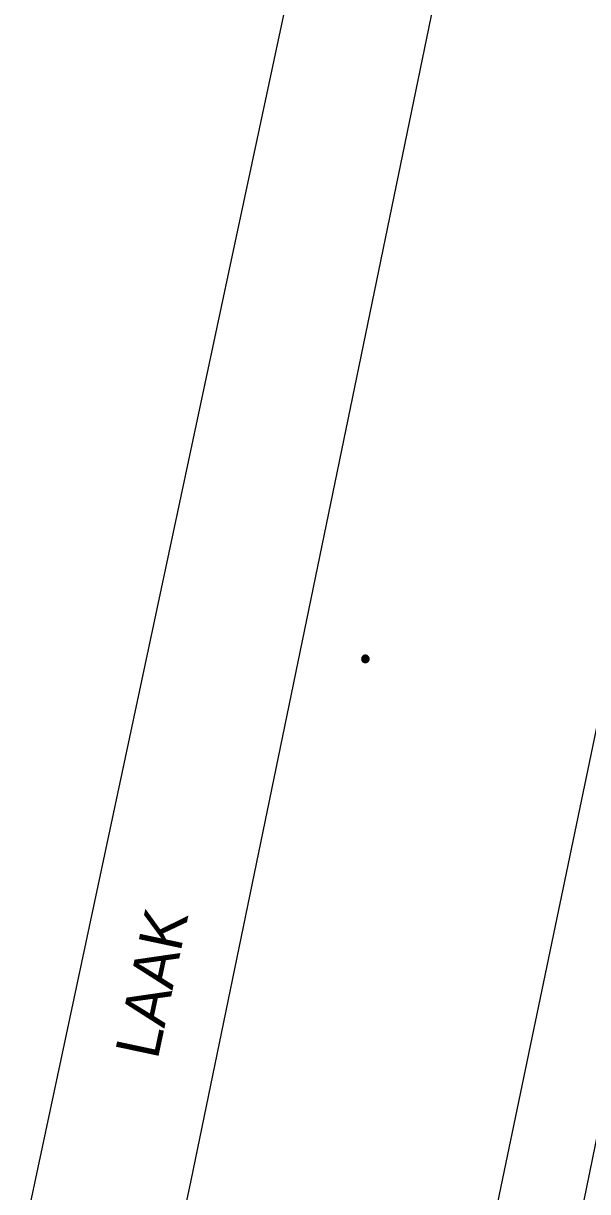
# Model space of a CAD drawing. Extents: x 81065 to 81486, y 452384 to 452681.
# Drawn here: x 81256.82 to 81276.27, y 452560.19 to 452600.46 of the extents above; entities that cross this region are included whole.
import ezdxf

# ---------------------------------------------------------------- set-up
doc = ezdxf.new("R2010")
doc.units = 0
for name, color, linetype in [('B-BH-AL-TOPOGRAFIE_STRAATNAAM-S', 7, 'Continuous'), ('B-BH-GR-BOOM-S', 7, 'Continuous'), ('B-BH-GR-GROENVOORZIENING-GV', 7, 'Continuous'), ('B-BH-VH-KANTOPSLUITING-GV', 7, 'Continuous')]:
    doc.layers.add(name, color=color, linetype=linetype)

msp = doc.modelspace()

# ---------------------------------------------------------------- linework, layer by layer
at = {"layer": 'B-BH-GR-BOOM-S'}
for points in [[(81268.479, 452578.55), (81268.48, 452578.536), (81268.482, 452578.523), (81268.485, 452578.51), (81268.49, 452578.498), (81268.496, 452578.486), (81268.504, 452578.474), (81268.512, 452578.464), (81268.522, 452578.454), (81268.532, 452578.446), (81268.544, 452578.438), (81268.556, 452578.432), (81268.568, 452578.427), (81268.581, 452578.424), (81268.594, 452578.422), (81268.608, 452578.421), (81268.621, 452578.422), (81268.635, 452578.424), (81268.648, 452578.427), (81268.66, 452578.432), (81268.672, 452578.438), (81268.684, 452578.446), (81268.694, 452578.454), (81268.704, 452578.464), (81268.712, 452578.474), (81268.72, 452578.486), (81268.726, 452578.498), (81268.73, 452578.51), (81268.734, 452578.523), (81268.736, 452578.536), (81268.737, 452578.55), (81268.736, 452578.563), (81268.734, 452578.577), (81268.73, 452578.59), (81268.726, 452578.602), (81268.72, 452578.614), (81268.712, 452578.626), (81268.704, 452578.636), (81268.694, 452578.646), (81268.684, 452578.654), (81268.672, 452578.662), (81268.66, 452578.668), (81268.648, 452578.672), (81268.635, 452578.676), (81268.621, 452578.678), (81268.608, 452578.679), (81268.594, 452578.678), (81268.581, 452578.676), (81268.568, 452578.672), (81268.556, 452578.668), (81268.544, 452578.662), (81268.532, 452578.654), (81268.522, 452578.646), (81268.512, 452578.636), (81268.504, 452578.626), (81268.496, 452578.614), (81268.49, 452578.602), (81268.485, 452578.59), (81268.482, 452578.577), (81268.48, 452578.563), (81268.479, 452578.55)], [(81268.504, 452578.55), (81268.504, 452578.539), (81268.506, 452578.528), (81268.509, 452578.518), (81268.513, 452578.507), (81268.517, 452578.498), (81268.523, 452578.489), (81268.53, 452578.48), (81268.538, 452578.472), (81268.547, 452578.465), (81268.556, 452578.459), (81268.565, 452578.455), (81268.576, 452578.451), (81268.586, 452578.448), (81268.597, 452578.446), (81268.608, 452578.446), (81268.619, 452578.446), (81268.63, 452578.448), (81268.64, 452578.451), (81268.65, 452578.455), (81268.66, 452578.459), (81268.669, 452578.465), (81268.678, 452578.472), (81268.686, 452578.48), (81268.692, 452578.489), (81268.698, 452578.498), (81268.703, 452578.507), (81268.707, 452578.518), (81268.71, 452578.528), (81268.712, 452578.539), (81268.712, 452578.55), (81268.712, 452578.561), (81268.71, 452578.572), (81268.707, 452578.582), (81268.703, 452578.592), (81268.698, 452578.602), (81268.692, 452578.611), (81268.686, 452578.62), (81268.678, 452578.628), (81268.669, 452578.634), (81268.66, 452578.64), (81268.65, 452578.645), (81268.64, 452578.649), (81268.63, 452578.652), (81268.619, 452578.654), (81268.608, 452578.654), (81268.597, 452578.654), (81268.586, 452578.652), (81268.576, 452578.649), (81268.565, 452578.645), (81268.556, 452578.64), (81268.547, 452578.634), (81268.538, 452578.628), (81268.53, 452578.62), (81268.523, 452578.611), (81268.517, 452578.602), (81268.513, 452578.592), (81268.509, 452578.582), (81268.506, 452578.572), (81268.504, 452578.561), (81268.504, 452578.55)], [(81268.526, 452578.55), (81268.527, 452578.541), (81268.528, 452578.533), (81268.53, 452578.525), (81268.533, 452578.517), (81268.537, 452578.509), (81268.542, 452578.502), (81268.547, 452578.495), (81268.553, 452578.489), (81268.56, 452578.484), (81268.567, 452578.479), (81268.575, 452578.475), (81268.583, 452578.472), (81268.591, 452578.47), (81268.599, 452578.469), (81268.608, 452578.468), (81268.616, 452578.469), (81268.625, 452578.47), (81268.633, 452578.472), (81268.641, 452578.475), (81268.649, 452578.479), (81268.656, 452578.484), (81268.663, 452578.489), (81268.669, 452578.495), (81268.674, 452578.502), (81268.679, 452578.509), (81268.682, 452578.517), (81268.686, 452578.525), (81268.688, 452578.533), (81268.689, 452578.541), (81268.69, 452578.55), (81268.689, 452578.558), (81268.688, 452578.567), (81268.686, 452578.575), (81268.682, 452578.583), (81268.679, 452578.591), (81268.674, 452578.598), (81268.669, 452578.605), (81268.663, 452578.611), (81268.656, 452578.616), (81268.649, 452578.621), (81268.641, 452578.624), (81268.633, 452578.628), (81268.625, 452578.63), (81268.616, 452578.631), (81268.608, 452578.632), (81268.599, 452578.631), (81268.591, 452578.63), (81268.583, 452578.628), (81268.575, 452578.624), (81268.567, 452578.621), (81268.56, 452578.616), (81268.553, 452578.611), (81268.547, 452578.605), (81268.542, 452578.598), (81268.537, 452578.591), (81268.533, 452578.583), (81268.53, 452578.575), (81268.528, 452578.567), (81268.527, 452578.558), (81268.526, 452578.55)], [(81268.549, 452578.55), (81268.55, 452578.544), (81268.551, 452578.538), (81268.552, 452578.532), (81268.554, 452578.526), (81268.557, 452578.521), (81268.561, 452578.515), (81268.564, 452578.511), (81268.569, 452578.506), (81268.573, 452578.503), (81268.579, 452578.499), (81268.584, 452578.496), (81268.59, 452578.494), (81268.596, 452578.493), (81268.602, 452578.492), (81268.608, 452578.491), (81268.614, 452578.492), (81268.62, 452578.493), (81268.626, 452578.494), (81268.632, 452578.496), (81268.637, 452578.499), (81268.642, 452578.503), (81268.647, 452578.506), (81268.652, 452578.511), (81268.655, 452578.515), (81268.659, 452578.521), (81268.662, 452578.526), (81268.664, 452578.532), (81268.665, 452578.538), (81268.666, 452578.544), (81268.667, 452578.55), (81268.666, 452578.556), (81268.665, 452578.562), (81268.664, 452578.568), (81268.662, 452578.574), (81268.659, 452578.579), (81268.655, 452578.584), (81268.652, 452578.589), (81268.647, 452578.594), (81268.642, 452578.597), (81268.637, 452578.601), (81268.632, 452578.604), (81268.626, 452578.606), (81268.62, 452578.607), (81268.614, 452578.608), (81268.608, 452578.609), (81268.602, 452578.608), (81268.596, 452578.607), (81268.59, 452578.606), (81268.584, 452578.604), (81268.579, 452578.601), (81268.573, 452578.597), (81268.569, 452578.594), (81268.564, 452578.589), (81268.561, 452578.584), (81268.557, 452578.579), (81268.554, 452578.574), (81268.552, 452578.568), (81268.551, 452578.562), (81268.55, 452578.556), (81268.549, 452578.55)], [(81268.572, 452578.55), (81268.572, 452578.546), (81268.573, 452578.543), (81268.574, 452578.539), (81268.575, 452578.535), (81268.577, 452578.532), (81268.579, 452578.529), (81268.581, 452578.526), (81268.584, 452578.523), (81268.587, 452578.521), (81268.59, 452578.519), (81268.593, 452578.517), (81268.597, 452578.516), (81268.601, 452578.515), (81268.604, 452578.514), (81268.608, 452578.514), (81268.612, 452578.514), (81268.615, 452578.515), (81268.619, 452578.516), (81268.623, 452578.517), (81268.626, 452578.519), (81268.629, 452578.521), (81268.632, 452578.523), (81268.634, 452578.526), (81268.637, 452578.529), (81268.639, 452578.532), (81268.641, 452578.535), (81268.642, 452578.539), (81268.643, 452578.543), (81268.644, 452578.546), (81268.644, 452578.55), (81268.644, 452578.554), (81268.643, 452578.557), (81268.642, 452578.561), (81268.641, 452578.565), (81268.639, 452578.568), (81268.637, 452578.571), (81268.634, 452578.574), (81268.632, 452578.576), (81268.629, 452578.579), (81268.626, 452578.581), (81268.623, 452578.583), (81268.619, 452578.584), (81268.615, 452578.585), (81268.612, 452578.586), (81268.608, 452578.586), (81268.604, 452578.586), (81268.601, 452578.585), (81268.597, 452578.584), (81268.593, 452578.583), (81268.59, 452578.581), (81268.587, 452578.579), (81268.584, 452578.576), (81268.581, 452578.574), (81268.579, 452578.571), (81268.577, 452578.568), (81268.575, 452578.565), (81268.574, 452578.561), (81268.573, 452578.557), (81268.572, 452578.554), (81268.572, 452578.55)], [(81268.595, 452578.55), (81268.595, 452578.549), (81268.595, 452578.547), (81268.596, 452578.546), (81268.596, 452578.545), (81268.597, 452578.544), (81268.598, 452578.542), (81268.598, 452578.541), (81268.599, 452578.54), (81268.6, 452578.54), (81268.602, 452578.539), (81268.603, 452578.538), (81268.604, 452578.538), (81268.605, 452578.537), (81268.607, 452578.537), (81268.608, 452578.537), (81268.609, 452578.537), (81268.611, 452578.537), (81268.612, 452578.538), (81268.613, 452578.538), (81268.614, 452578.539), (81268.616, 452578.54), (81268.617, 452578.54), (81268.618, 452578.541), (81268.618, 452578.542), (81268.619, 452578.544), (81268.62, 452578.545), (81268.62, 452578.546), (81268.621, 452578.547), (81268.621, 452578.549), (81268.621, 452578.55), (81268.621, 452578.551), (81268.621, 452578.553), (81268.62, 452578.554), (81268.62, 452578.555), (81268.619, 452578.556), (81268.618, 452578.558), (81268.618, 452578.559), (81268.617, 452578.56), (81268.616, 452578.56), (81268.614, 452578.561), (81268.613, 452578.562), (81268.612, 452578.562), (81268.611, 452578.563), (81268.609, 452578.563), (81268.608, 452578.563), (81268.607, 452578.563), (81268.605, 452578.563), (81268.604, 452578.562), (81268.603, 452578.562), (81268.602, 452578.561), (81268.6, 452578.56), (81268.599, 452578.56), (81268.598, 452578.559), (81268.598, 452578.558), (81268.597, 452578.556), (81268.596, 452578.555), (81268.596, 452578.554), (81268.595, 452578.553), (81268.595, 452578.551), (81268.595, 452578.55)]]:
    msp.add_lwpolyline(points, dxfattribs=at)
at = {"layer": 'B-BH-GR-GROENVOORZIENING-GV'}
for points in [[(81251.835, 452535.75), (81252.192, 452536.931), (81257.329, 452561.023), (81263.916, 452591.926), (81268.85, 452615.069)], [(81272.849, 452614.237), (81272.75, 452609.812), (81262.594, 452560.576), (81261.543, 452555.691), (81260.53, 452550.798), (81257.699, 452536.499), (81257.241, 452535.02)]]:
    msp.add_lwpolyline(points, dxfattribs=at)
at = {"layer": 'B-BH-VH-KANTOPSLUITING-GV'}
for points in [[(81267.731, 452533.684), (81282.916, 452606.564), (81283.089, 452607.976)], [(81279.537, 452567.844), (81277.84, 452568.205), (81274.621, 452552.477), (81276.314, 452552.171)]]:
    msp.add_lwpolyline(points, dxfattribs=at)

# ---------------------------------------------------------------- texts
at = {"layer": 'B-BH-AL-TOPOGRAFIE_STRAATNAAM-S'}
msp.add_text('LAAK', height=1.5, rotation=77.9965, dxfattribs=at).set_placement((81261.443, 452564.708))

doc.saveas('drawing.dxf')
